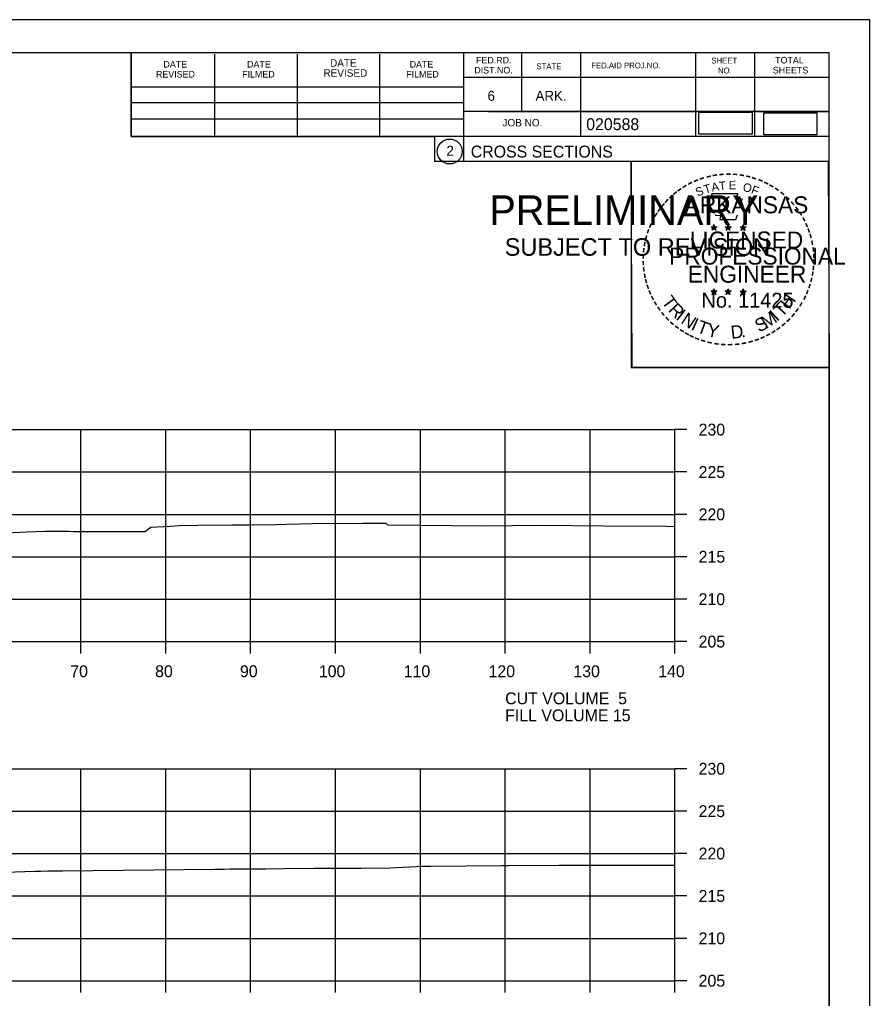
# Model space of a CAD drawing. Extents: x 1368968 to 1369915, y 377395 to 380381.
# Drawn here: x 1369814.5 to 1369914.7, y 378986 to 379101.4 of the extents above; entities that cross this region are included whole.
import ezdxf

# ---------------------------------------------------------------- set-up
doc = ezdxf.new("R2010")
doc.units = 0
for name, color, linetype in [('Default', 7, 'Continuous'), ('S_BREAKLINE_ANNOT', 7, 'Continuous'), ('S_BRIDGE', 7, 'Continuous'), ('S_BRIDGE_ANNOT', 7, 'Continuous'), ('S_BUILDING_ANNOT', 7, 'Continuous'), ('S_CAL_CORNER', 7, 'Continuous'), ('S_CTL_TABLE', 7, 'Continuous'), ('S_DITCHLINE_ANNOT', 7, 'Continuous'), ('S_DROP_INLET', 7, 'Continuous')]:
    doc.layers.add(name, color=color, linetype=linetype)

msp = doc.modelspace()

# ---------------------------------------------------------------- linework, layer by layer
at = {"layer": 'Default'}
for points in [[(1369894.57, 379087.91), (1369900.91, 379087.91), (1369900.91, 379090.43), (1369894.57, 379090.43)], [(1369902.22, 379087.83), (1369908.56, 379087.83), (1369908.56, 379090.35), (1369902.22, 379090.35)]]:
    msp.add_lwpolyline(points, close=True, dxfattribs=at)
at = {"layer": 'S_BREAKLINE_ANNOT'}
for p, q in [((1369891.78, 379028.04), (1369891.78, 379053.04)), ((1369893.18, 379053.04), (1369891.78, 379053.04)), ((1369893.18, 379048.04), (1369891.78, 379048.04)), ((1369893.18, 379043.04), (1369891.78, 379043.04)), ((1369893.18, 379038.04), (1369891.78, 379038.04)), ((1369893.18, 379033.04), (1369891.78, 379033.04)), ((1369611.78, 379028.04), (1369891.78, 379028.04)), ((1369821.78, 379026.64), (1369821.78, 379028.04)), ((1369831.78, 379026.64), (1369831.78, 379028.04)), ((1369841.78, 379026.64), (1369841.78, 379028.04)), ((1369851.78, 379026.64), (1369851.78, 379028.04)), ((1369861.78, 379026.64), (1369861.78, 379028.04)), ((1369871.78, 379026.64), (1369871.78, 379028.04)), ((1369881.78, 379026.64), (1369881.78, 379028.04)), ((1369891.78, 379026.64), (1369891.78, 379028.04)), ((1369893.18, 379028.04), (1369891.78, 379028.04)), ((1369891.78, 378988.04), (1369891.78, 379013.04)), ((1369893.18, 379013.04), (1369891.78, 379013.04)), ((1369893.18, 379008.04), (1369891.78, 379008.04)), ((1369893.18, 379003.04), (1369891.78, 379003.04)), ((1369893.18, 378998.04), (1369891.78, 378998.04)), ((1369893.18, 378993.04), (1369891.78, 378993.04)), ((1369611.78, 378988.04), (1369891.78, 378988.04)), ((1369821.78, 378986.64), (1369821.78, 378988.04)), ((1369831.78, 378986.64), (1369831.78, 378988.04)), ((1369841.78, 378986.64), (1369841.78, 378988.04)), ((1369851.78, 378986.64), (1369851.78, 378988.04)), ((1369861.78, 378986.64), (1369861.78, 378988.04)), ((1369871.78, 378986.64), (1369871.78, 378988.04)), ((1369881.78, 378986.64), (1369881.78, 378988.04)), ((1369891.78, 378986.64), (1369891.78, 378988.04)), ((1369893.18, 378988.04), (1369891.78, 378988.04))]:
    msp.add_line(p, q, dxfattribs=at)
at = {"layer": 'S_BRIDGE_ANNOT'}
for p, q in [((1369593.78, 379097.5), (1369909.96, 379097.5)), ((1369827.7, 379087.62), (1369827.7, 379097.5)), ((1369837.56, 379087.62), (1369837.56, 379097.3)), ((1369847.32, 379087.62), (1369847.32, 379097.3)), ((1369857, 379087.62), (1369857, 379097.3)), ((1369866.86, 379097.5), (1369866.86, 379084.7)), ((1369873.7, 379097.5), (1369873.7, 379090.56)), ((1369880.64, 379097.5), (1369880.64, 379087.62)), ((1369894.22, 379097.5), (1369894.22, 379087.62)), ((1369901.16, 379097.5), (1369901.16, 379087.62)), ((1369909.96, 378892.04), (1369909.96, 379097.5)), ((1369827.7, 379093.48), (1369866.86, 379093.48)), ((1369909.96, 379094.56), (1369866.86, 379094.56)), ((1369909.96, 379094.58), (1369909.96, 379094.58)), ((1369827.7, 379091.62), (1369866.86, 379091.62)), ((1369909.96, 379090.56), (1369866.86, 379090.56)), ((1369869.82, 379090.56), (1369909.96, 379090.56)), ((1369827.7, 379087.62), (1369827.7, 379089.68)), ((1369827.7, 379089.68), (1369866.86, 379089.68)), ((1369909.96, 379087.62), (1369827.7, 379087.62)), ((1369866.86, 379084.7), (1369909.96, 379084.7))]:
    msp.add_line(p, q, dxfattribs=at)
msp.add_circle((1369865.24, 379085.84), 1.47, dxfattribs=at)
at = {"layer": 'S_BUILDING_ANNOT'}
for p, q in [((1369896.04, 379076.96), (1369896.39, 379076.85)), ((1369896.04, 379076.96), (1369896.29, 379076.91)), ((1369896.04, 379076.96), (1369896.28, 379076.84)), ((1369896.17, 379076.55), (1369896.39, 379076.85)), ((1369896.17, 379076.55), (1369896.3, 379076.79)), ((1369896.17, 379076.55), (1369896.39, 379076.77)), ((1369896.39, 379077.21), (1369896.35, 379076.96)), ((1369896.39, 379076.85), (1369896.39, 379077.21)), ((1369896.39, 379077.21), (1369896.44, 379076.96)), ((1369896.74, 379076.96), (1369896.39, 379076.85)), ((1369896.6, 379076.55), (1369896.39, 379076.85)), ((1369896.6, 379076.55), (1369896.39, 379076.76)), ((1369896.74, 379076.96), (1369896.45, 379076.91)), ((1369896.6, 379076.55), (1369896.47, 379076.84)), ((1369896.74, 379076.96), (1369896.53, 379076.86)), ((1369897.71, 379076.96), (1369898.06, 379076.85)), ((1369897.71, 379076.96), (1369897.96, 379076.91)), ((1369897.71, 379076.96), (1369897.95, 379076.84)), ((1369897.84, 379076.55), (1369898.06, 379076.85)), ((1369897.84, 379076.55), (1369897.97, 379076.79)), ((1369897.84, 379076.55), (1369898.06, 379076.77)), ((1369898.06, 379077.21), (1369898.02, 379076.96)), ((1369898.06, 379076.85), (1369898.06, 379077.21)), ((1369898.06, 379077.21), (1369898.11, 379076.96)), ((1369898.41, 379076.96), (1369898.06, 379076.85)), ((1369898.27, 379076.55), (1369898.06, 379076.85)), ((1369898.27, 379076.55), (1369898.06, 379076.76)), ((1369898.41, 379076.96), (1369898.12, 379076.91)), ((1369898.27, 379076.55), (1369898.14, 379076.84)), ((1369898.41, 379076.96), (1369898.2, 379076.86)), ((1369899.48, 379076.95), (1369899.82, 379076.84)), ((1369899.48, 379076.95), (1369899.73, 379076.9)), ((1369899.48, 379076.95), (1369899.71, 379076.82)), ((1369899.61, 379076.54), (1369899.82, 379076.84)), ((1369899.61, 379076.54), (1369899.73, 379076.78)), ((1369899.61, 379076.54), (1369899.82, 379076.76)), ((1369899.82, 379077.2), (1369899.78, 379076.95)), ((1369899.82, 379076.84), (1369899.82, 379077.2)), ((1369899.82, 379077.2), (1369899.87, 379076.95)), ((1369900.17, 379076.95), (1369899.82, 379076.84)), ((1369900.04, 379076.54), (1369899.82, 379076.84)), ((1369900.04, 379076.54), (1369899.82, 379076.75)), ((1369900.17, 379076.95), (1369899.89, 379076.9)), ((1369900.04, 379076.54), (1369899.9, 379076.83)), ((1369900.17, 379076.95), (1369899.97, 379076.84)), ((1369896.04, 379069.39), (1369896.39, 379069.27)), ((1369896.04, 379069.39), (1369896.29, 379069.34)), ((1369896.04, 379069.39), (1369896.27, 379069.26)), ((1369896.17, 379068.98), (1369896.39, 379069.27)), ((1369896.17, 379068.98), (1369896.3, 379069.22)), ((1369896.39, 379069.64), (1369896.35, 379069.39)), ((1369896.39, 379069.27), (1369896.39, 379069.64)), ((1369896.39, 379069.64), (1369896.44, 379069.39)), ((1369896.73, 379069.39), (1369896.39, 379069.27)), ((1369896.6, 379068.98), (1369896.39, 379069.27)), ((1369896.73, 379069.39), (1369896.45, 379069.34)), ((1369896.6, 379068.98), (1369896.46, 379069.27)), ((1369896.73, 379069.39), (1369896.53, 379069.28)), ((1369897.71, 379069.39), (1369898.06, 379069.27)), ((1369897.71, 379069.39), (1369897.96, 379069.34)), ((1369897.71, 379069.39), (1369897.94, 379069.26)), ((1369897.84, 379068.98), (1369898.06, 379069.27)), ((1369897.84, 379068.98), (1369897.97, 379069.22)), ((1369898.06, 379069.64), (1369898.01, 379069.39)), ((1369898.06, 379069.27), (1369898.06, 379069.64)), ((1369898.06, 379069.64), (1369898.1, 379069.39)), ((1369898.4, 379069.39), (1369898.06, 379069.27)), ((1369898.27, 379068.98), (1369898.06, 379069.27)), ((1369898.4, 379069.39), (1369898.12, 379069.34)), ((1369898.27, 379068.98), (1369898.13, 379069.27)), ((1369898.4, 379069.39), (1369898.2, 379069.28)), ((1369899.47, 379069.38), (1369899.82, 379069.26)), ((1369899.47, 379069.38), (1369899.73, 379069.33)), ((1369899.47, 379069.38), (1369899.71, 379069.25)), ((1369899.61, 379068.97), (1369899.82, 379069.26)), ((1369899.61, 379068.97), (1369899.73, 379069.21)), ((1369899.82, 379069.63), (1369899.78, 379069.38)), ((1369899.82, 379069.26), (1369899.82, 379069.63)), ((1369899.82, 379069.63), (1369899.87, 379069.38)), ((1369900.17, 379069.38), (1369899.82, 379069.26)), ((1369900.04, 379068.97), (1369899.82, 379069.26)), ((1369900.17, 379069.38), (1369899.88, 379069.33)), ((1369900.04, 379068.97), (1369899.9, 379069.26)), ((1369900.17, 379069.38), (1369899.97, 379069.27)), ((1369896.17, 379068.98), (1369896.38, 379069.19)), ((1369896.6, 379068.98), (1369896.38, 379069.19)), ((1369897.84, 379068.98), (1369898.05, 379069.19)), ((1369898.27, 379068.98), (1369898.05, 379069.19)), ((1369899.61, 379068.97), (1369899.82, 379069.18)), ((1369900.04, 379068.97), (1369899.82, 379069.18))]:
    msp.add_line(p, q, dxfattribs=at)
for points in [[(1369896.08, 379080.84), (1369896.35, 379080.01)], [(1369899.59, 379079.91), (1369899.74, 379080.2), (1369899.05, 379080.17), (1369899.2, 379080.84), (1369896.08, 379080.84)], [(1369896.57, 379078.41), (1369896.57, 379078.33), (1369897.14, 379078.31), (1369897.08, 379077.83), (1369898.95, 379077.83), (1369899.15, 379078.37)], [(1369896.39, 379077.21), (1369896.6, 379076.55), (1369896.04, 379076.96), (1369896.74, 379076.96), (1369896.17, 379076.55), (1369896.39, 379077.21)], [(1369898.06, 379077.21), (1369898.27, 379076.55), (1369897.71, 379076.96), (1369898.41, 379076.96), (1369897.84, 379076.55), (1369898.06, 379077.21)], [(1369899.82, 379077.2), (1369900.04, 379076.54), (1369899.48, 379076.95), (1369900.17, 379076.95), (1369899.61, 379076.54), (1369899.82, 379077.2)], [(1369896.39, 379069.64), (1369896.6, 379068.98), (1369896.04, 379069.39), (1369896.73, 379069.39), (1369896.17, 379068.98), (1369896.39, 379069.64)], [(1369898.06, 379069.64), (1369898.27, 379068.98), (1369897.71, 379069.39), (1369898.4, 379069.39), (1369897.84, 379068.98), (1369898.06, 379069.64)], [(1369899.82, 379069.63), (1369900.04, 379068.97), (1369899.47, 379069.38), (1369900.17, 379069.38), (1369899.61, 379068.97), (1369899.82, 379069.63)]]:
    msp.add_lwpolyline(points, dxfattribs=at)
for centre, radius in [((1369896.39, 379076.85), 0.172), ((1369896.39, 379076.85), 0.145), ((1369896.39, 379076.85), 0.116), ((1369896.39, 379076.85), 0.0991), ((1369896.39, 379076.85), 0.0747), ((1369896.39, 379076.85), 0.0495), ((1369896.39, 379076.85), 0.0296), ((1369898.06, 379076.85), 0.172), ((1369898.06, 379076.85), 0.145), ((1369898.06, 379076.85), 0.116), ((1369898.06, 379076.85), 0.0991), ((1369898.06, 379076.85), 0.0747), ((1369898.06, 379076.85), 0.0495), ((1369898.06, 379076.85), 0.0296), ((1369899.82, 379076.83), 0.172), ((1369899.82, 379076.83), 0.145), ((1369899.82, 379076.83), 0.116), ((1369899.82, 379076.83), 0.0991), ((1369899.82, 379076.83), 0.0747), ((1369899.82, 379076.83), 0.0495), ((1369899.82, 379076.83), 0.0296), ((1369896.39, 379069.27), 0.172), ((1369896.39, 379069.27), 0.145), ((1369896.39, 379069.27), 0.116), ((1369896.39, 379069.27), 0.0991), ((1369896.39, 379069.27), 0.0747), ((1369896.39, 379069.27), 0.0495), ((1369896.39, 379069.27), 0.0296), ((1369898.05, 379069.27), 0.172), ((1369898.05, 379069.27), 0.145), ((1369898.05, 379069.27), 0.116), ((1369898.05, 379069.27), 0.0991), ((1369898.05, 379069.27), 0.0747), ((1369898.05, 379069.27), 0.0495), ((1369898.05, 379069.27), 0.0296), ((1369899.82, 379069.26), 0.172), ((1369899.82, 379069.26), 0.145), ((1369899.82, 379069.26), 0.116), ((1369899.82, 379069.26), 0.0991), ((1369899.82, 379069.26), 0.0747), ((1369899.82, 379069.26), 0.0495), ((1369899.82, 379069.26), 0.0296)]:
    msp.add_circle(centre, radius, dxfattribs=at)
at = {"layer": 'S_CTL_TABLE'}
for points in [[(1369807.92, 379040.63), (1369815.4, 379040.97), (1369817.54, 379041.07), (1369820.34, 379041.05), (1369820.91, 379041.04), (1369821.67, 379041.04), (1369822.44, 379041.03), (1369825.29, 379041.02), (1369827.88, 379041.01), (1369828.85, 379041.02), (1369829.34, 379041.02), (1369829.75, 379041.33), (1369830.02, 379041.55), (1369832.3, 379041.66), (1369833.34, 379041.71), (1369835.54, 379041.75), (1369839.63, 379041.79), (1369841.66, 379041.82), (1369844.82, 379041.86), (1369845.99, 379041.88), (1369849.06, 379041.95), (1369854.97, 379042), (1369857.43, 379042), (1369857.7, 379042.02), (1369857.81, 379041.94), (1369857.92, 379041.79), (1369869.26, 379041.7), (1369876.01, 379041.75), (1369883.38, 379041.69), (1369890.78, 379041.64), (1369891.78, 379041.62)], [(1369803.44, 379000.52), (1369816.33, 379000.95), (1369816.76, 379000.96), (1369817.05, 379000.97), (1369817.88, 379001.01), (1369818.9, 379001.02), (1369819.13, 379001.02), (1369819.6, 379001.02), (1369837.5, 379001.2), (1369838.64, 379001.21), (1369839.35, 379001.22), (1369841.13, 379001.24), (1369842.54, 379001.25), (1369843.56, 379001.25), (1369845.71, 379001.27), (1369849.21, 379001.3), (1369850.97, 379001.31), (1369852.23, 379001.32), (1369854.81, 379001.33), (1369858.23, 379001.36), (1369862.05, 379001.54), (1369862.96, 379001.54), (1369871.37, 379001.63), (1369872.16, 379001.63), (1369878.08, 379001.67), (1369891.78, 379001.65)]]:
    msp.add_lwpolyline(points, dxfattribs=at)
at = {"layer": 'S_DITCHLINE_ANNOT'}
for p, q in [((1369611.78, 379053.04), (1369891.78, 379053.04)), ((1369821.78, 379028.04), (1369821.78, 379053.04)), ((1369831.78, 379028.04), (1369831.78, 379053.04)), ((1369841.78, 379028.04), (1369841.78, 379053.04)), ((1369851.78, 379028.04), (1369851.78, 379053.04)), ((1369861.78, 379028.04), (1369861.78, 379053.04)), ((1369871.78, 379028.04), (1369871.78, 379053.04)), ((1369881.78, 379028.04), (1369881.78, 379053.04)), ((1369891.78, 379028.04), (1369891.78, 379053.04)), ((1369611.78, 379048.04), (1369891.78, 379048.04)), ((1369611.78, 379043.04), (1369891.78, 379043.04)), ((1369611.78, 379038.04), (1369891.78, 379038.04)), ((1369611.78, 379033.04), (1369891.78, 379033.04)), ((1369611.78, 379028.04), (1369891.78, 379028.04)), ((1369611.78, 379013.04), (1369891.78, 379013.04)), ((1369821.78, 378988.04), (1369821.78, 379013.04)), ((1369831.78, 378988.04), (1369831.78, 379013.04)), ((1369841.78, 378988.04), (1369841.78, 379013.04)), ((1369851.78, 378988.04), (1369851.78, 379013.04)), ((1369861.78, 378988.04), (1369861.78, 379013.04)), ((1369871.78, 378988.04), (1369871.78, 379013.04)), ((1369881.78, 378988.04), (1369881.78, 379013.04)), ((1369891.78, 378988.04), (1369891.78, 379013.04)), ((1369611.78, 379008.04), (1369891.78, 379008.04)), ((1369611.78, 379003.04), (1369891.78, 379003.04)), ((1369611.78, 378998.04), (1369891.78, 378998.04)), ((1369611.78, 378993.04), (1369891.78, 378993.04)), ((1369611.78, 378988.04), (1369891.78, 378988.04))]:
    msp.add_line(p, q, dxfattribs=at)
at = {"layer": 'S_DROP_INLET'}
for p, q in [((1369581.38, 379101.4), (1369914.71, 379101.4)), ((1369885.99, 379062.25), (1369885.99, 379062.25))]:
    msp.add_line(p, q, dxfattribs=at)
for points in [[(1369581.37, 379101.4), (1369914.71, 379101.4), (1369914.71, 378888.06), (1369581.37, 378888.06)], [(1369827.7, 379097.5), (1369827.7, 379087.62), (1369863.43, 379087.62), (1369863.43, 379084.7), (1369886.63, 379084.7), (1369886.63, 379060.37), (1369909.96, 379060.37), (1369909.96, 378892.04), (1369593.78, 378892.04), (1369593.78, 379097.5)], [(1369886.63, 379084.7), (1369909.84, 379084.7), (1369909.96, 379060.37), (1369886.75, 379060.37)]]:
    msp.add_lwpolyline(points, close=True, dxfattribs=at)

# ---------------------------------------------------------------- texts
at = {"layer": 'S_BRIDGE'}
for s, p in [('230', (1369894.58, 379052.34)), ('225', (1369894.58, 379047.34)), ('220', (1369894.58, 379042.34)), ('215', (1369894.58, 379037.34)), ('210', (1369894.58, 379032.34)), ('205', (1369894.58, 379027.34)), ('70', (1369820.52, 379023.84)), ('80', (1369830.52, 379023.84)), ('90', (1369840.52, 379023.84)), ('100', (1369849.82, 379023.84)), ('110', (1369859.82, 379023.84)), ('120', (1369869.82, 379023.84)), ('130', (1369879.82, 379023.84)), ('140', (1369889.82, 379023.84)), ('CUT VOLUME  5', (1369871.78, 379020.64)), ('FILL VOLUME 15', (1369871.78, 379018.64)), ('230', (1369894.58, 379012.34)), ('225', (1369894.58, 379007.34)), ('220', (1369894.58, 379002.34)), ('215', (1369894.58, 378997.34)), ('210', (1369894.58, 378992.34)), ('205', (1369894.58, 378987.34))]:
    msp.add_text(s, height=1.4, dxfattribs=at).set_placement(p)
at = {"layer": 'S_BRIDGE_ANNOT'}
for s, height, p in [('FED.RD.', 0.782, (1369868.34, 379096.22)), ('SHEET', 0.684, (1369896.08, 379096.22)), ('TOTAL', 0.782, (1369903.6, 379096.22)), ('DATE', 0.782, (1369831.5, 379095.74)), ('DATE', 0.782, (1369841.36, 379095.74)), ('DATE', 0.879, (1369851.14, 379095.84)), ('DATE', 0.782, (1369860.52, 379095.74)), ('DIST.NO.', 0.782, (1369868.14, 379095.04)), ('STATE', 0.684, (1369875.46, 379095.54)), ('FED.AID PROJ.NO.', 0.684, (1369881.92, 379095.64)), ('SHEETS', 0.782, (1369903.32, 379095.04)), ('REVISED', 0.782, (1369830.62, 379094.56)), ('FILMED', 0.782, (1369840.78, 379094.56)), ('REVISED', 0.879, (1369850.36, 379094.66)), ('FILMED', 0.782, (1369860.12, 379094.56)), ('NO.', 0.684, (1369896.86, 379095.04)), ('6', 1.17, (1369869.7, 379091.82)), ('ARK.', 1.172, (1369875.36, 379091.82)), ('JOB NO.', 0.879, (1369871.46, 379088.8)), ('020588', 1.4, (1369881.33, 379088.36)), ('2', 1.17, (1369864.86, 379085.35)), ('CROSS SECTIONS', 1.4, (1369867.72, 379085.13))]:
    msp.add_text(s, height=height, rotation=360, dxfattribs=at).set_placement(p)
at = {"layer": 'S_BUILDING_ANNOT'}
for s, height, rotation, p in [('-', 1.6, 10.2193, (1369896.26, 379082.37)), ('-', 1.6, 5.8968, (1369896.99, 379082.48)), ('-', 1.6, 0.1862, (1369897.76, 379082.55)), ('-', 1.6, 357.743, (1369898.48, 379082.54)), ('-', 1.6, 352.1617, (1369899.23, 379082.48)), ('-', 1.6, 34.0636, (1369892.97, 379081.01)), ('-', 1.6, 28.7918, (1369893.56, 379081.38)), ('-', 1.6, 24.3072, (1369894.2, 379081.69)), ('-', 1.6, 19.1761, (1369894.83, 379081.96)), ('T', 1, 16.4036, (1369895.35, 379080.85)), ('-', 1.6, 13.6301, (1369895.58, 379082.2)), ('A', 1, 11.2132, (1369896.18, 379081.1)), ('T', 1, 6.0228, (1369897.03, 379081.26)), ('E', 1, 0.8323, (1369898.13, 379081.37)), ('O', 1, 350.4515, (1369899.74, 379081.16)), ('-', 1.6, 347.2049, (1369899.95, 379082.37)), ('-', 1.6, 342.3362, (1369900.58, 379082.21)), ('-', 1.6, 337.8551, (1369901.32, 379081.99)), ('-', 1.6, 334.1211, (1369901.95, 379081.72)), ('-', 1.6, 329.6409, (1369902.53, 379081.43)), ('-', 1.6, 42.9622, (1369891.48, 379079.82)), ('-', 1.6, 38.9507, (1369891.91, 379080.23)), ('-', 1.6, 36.2317, (1369892.39, 379080.61)), ('S', 1, 21.594, (1369894.44, 379080.51)), ('F', 1, 340.0707, (1369900.69, 379080.93)), ('-', 1.6, 325.8627, (1369903.17, 379081.07)), ('-', 1.6, 320.5297, (1369903.78, 379080.65)), ('-', 1.6, 50.6142, (1369890.63, 379078.85)), ('-', 1.6, 48.423, (1369891.03, 379079.34)), ('ARKANSAS', 2, 360, (1369892.94, 379078.55)), ('-', 1.6, 315.5786, (1369904.38, 379080.16)), ('-', 1.6, 309.8797, (1369904.95, 379079.61)), ('-', 1.6, 58.0706, (1369889.89, 379077.76)), ('-', 1.6, 54.2325, (1369890.22, 379078.29)), ('-', 1.6, 306.6522, (1369905.47, 379079.01)), ('-', 1.4, 303.6753, (1369905.96, 379078.44)), ('-', 1.6, 67.7743, (1369889.32, 379076.53)), ('-', 1.6, 62.8713, (1369889.58, 379077.15)), ('-', 1.6, 299.6684, (1369906.28, 379077.83)), ('-', 1.6, 294.6628, (1369906.6, 379077.22)), ('-', 1.6, 72.3945, (1369889.1, 379075.9)), ('LICENSED', 2, 360, (1369893.53, 379074.4)), ('DWB', 0.01, 360, (1369896.38, 379076.84)), ('DWB', 0.01, 360, (1369898.05, 379076.84)), ('DWB', 0.01, 360, (1369899.81, 379076.83)), ('-', 1.6, 290.5728, (1369906.86, 379076.64)), ('-', 1.6, 285.1233, (1369907.09, 379076.06)), ('-', 1.6, 81.2013, (1369888.77, 379074.48)), ('-', 1.6, 75.461, (1369888.9, 379075.19)), ('-', 1.6, 280.5493, (1369907.29, 379075.32)), ('-', 1.6, 85.1863, (1369888.69, 379073.79)), ('PROFESSIONAL', 2, 360, (1369891.11, 379072.5)), ('-', 1.6, 276.5962, (1369907.45, 379074.55)), ('-', 1.6, 94.1959, (1369888.7, 379072.36)), ('-', 1.6, 89.0622, (1369888.67, 379073.09)), ('-', 1.6, 274.3301, (1369907.51, 379073.83)), ('-', 1.6, 269.9407, (1369907.55, 379073.2)), ('-', 1.6, 98.9479, (1369888.78, 379071.69)), ('ENGINEER', 2, 360, (1369893.3, 379070.37)), ('-', 1.6, 260.9953, (1369907.46, 379071.88)), ('-', 1.6, 263.5172, (1369907.53, 379072.53)), ('-', 1.6, 101.7149, (1369888.91, 379070.96)), ('-', 1.6, 105.4578, (1369889.07, 379070.37)), ('-', 1.6, 255.7626, (1369907.35, 379071.2)), ('-', 1.6, 109.0874, (1369889.29, 379069.73)), ('-', 1.6, 114.0643, (1369889.54, 379069.14)), ('No. 11425', 1.757, 360, (1369894.92, 379067.42)), ('DWB', 0.01, 360, (1369896.37, 379069.27)), ('DWB', 0.01, 360, (1369898.04, 379069.27)), ('DWB', 0.01, 360, (1369899.81, 379069.26)), ('-', 1.6, 247.8887, (1369906.94, 379069.81)), ('-', 1.6, 252.8681, (1369907.17, 379070.48)), ('-', 1.6, 115.7289, (1369889.85, 379068.52)), ('-', 1.6, 120.4471, (1369890.2, 379067.93)), ('T', 1.54, 306.0406, (1369890.15, 379068.11)), ('T', 1.54, 46.6444, (1369904.38, 379066.21)), ('H', 1.54, 54.6088, (1369905.27, 379067.15)), ('-', 1.6, 239.0712, (1369906.29, 379068.43)), ('-', 1.6, 244.6197, (1369906.68, 379069.18)), ('-', 1.6, 125.8934, (1369890.61, 379067.37)), ('-', 1.6, 130.7181, (1369891.07, 379066.82)), ('R', 1.54, 314.005, (1369890.91, 379067.06)), ('I', 1.54, 321.9694, (1369891.81, 379066.13)), ('M', 1.54, 32.6563, (1369902.53, 379064.88)), ('I', 1.54, 42.1136, (1369903.81, 379065.73)), ('-', 1.6, 233.8452, (1369905.89, 379067.77)), ('-', 1.6, 134.2238, (1369891.59, 379066.28)), ('-', 1.6, 138.9338, (1369892.11, 379065.81)), ('N', 1.54, 326.5002, (1369892.38, 379065.66)), ('I', 1.54, 335.3603, (1369893.58, 379064.87)), ('T', 1.54, 339.8912, (1369894.25, 379064.55)), ('S', 1.54, 26.9312, (1369901.69, 379064.47)), ('-', 1.6, 225.7653, (1369904.98, 379066.64)), ('-', 1.6, 231.2538, (1369905.46, 379067.21)), ('-', 1.6, 144.6463, (1369892.67, 379065.41)), ('-', 1.6, 148.0898, (1369893.23, 379065.04)), ('Y', 1.54, 347.8556, (1369895.46, 379064.1)), ('D', 1.54, 6.3969, (1369898.45, 379063.74)), ('-', 1.6, 212.2491, (1369903.37, 379065.28)), ('-', 1.6, 215.7363, (1369903.91, 379065.66)), ('-', 1.6, 221.0851, (1369904.45, 379066.13)), ('-', 1.6, 151.5704, (1369893.81, 379064.71)), ('-', 1.6, 154.6002, (1369894.33, 379064.46)), ('-', 1.6, 158.5612, (1369894.95, 379064.21)), ('-', 1.6, 162.7983, (1369895.64, 379064)), ('-', 1.6, 167.5555, (1369896.36, 379063.83)), ('.', 1.54, 13.7642, (1369899.64, 379063.87)), ('-', 1.6, 195.4743, (1369900.89, 379064.1)), ('-', 1.6, 200.7184, (1369901.57, 379064.34)), ('-', 1.6, 204.2516, (1369902.19, 379064.61)), ('-', 1.6, 207.3568, (1369902.81, 379064.93)), ('-', 1.6, 173.1155, (1369897.13, 379063.72)), ('-', 1.6, 176.5183, (1369897.88, 379063.67)), ('-', 1.6, 181.5918, (1369898.62, 379063.69)), ('-', 1.6, 185.8167, (1369899.43, 379063.76)), ('-', 1.6, 191.2858, (1369900.16, 379063.9))]:
    msp.add_text(s, height=height, rotation=rotation, dxfattribs=at).set_placement(p)
at = {"layer": 'S_CAL_CORNER'}
for s, height, p in [('PRELIMINARY', 3.5, (1369869.91, 379077.17)), ('DWB', 0.01, (1369870.65, 379079.02)), ('SUBJECT TO REVISION', 2.0751, (1369871.72, 379073.54))]:
    msp.add_text(s, height=height, rotation=360, dxfattribs=at).set_placement(p)

doc.saveas('drawing.dxf')
